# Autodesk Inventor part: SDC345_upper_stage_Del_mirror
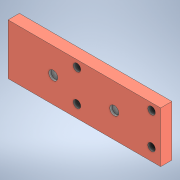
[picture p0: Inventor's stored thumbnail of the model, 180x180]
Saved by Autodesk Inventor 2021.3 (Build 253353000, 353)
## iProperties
Created: 2022-02
Part Number: SDC345_upper_stage_Del_mirror
Material: 一般
Document SubType Name: Modeling
Designer: kengo
Density: 1 g/cm^3
Appearance: 既定
Author: kengo
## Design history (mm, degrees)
derived "SDC_upper_stage_CFPlate.ipt"
feature "ソリッド1::SDC_upper_stage_CFPlate.ipt" dims "d0" = 10
tag "TaggingFeature1"
node "ソリッド1"
